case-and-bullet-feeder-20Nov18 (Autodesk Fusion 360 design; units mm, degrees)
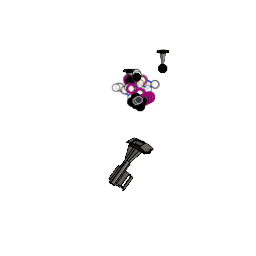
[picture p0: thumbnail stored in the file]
named bodies: "mk1j-bullet-base-feeder-beta", "mk1b-nose-guide", "mk1-flip-ramp", "mk1d-nose-guide-spacer", "mk2b-collator-plate-223", "mk1L-case-feeder-base-6-9", "mk1b-obsolete-case-feeder-base-centre", "mk1c-base-plate-attach", "mk1-case-to-pole-top", "mk1c-base-to-slinky-223cal-flange", "mk1j-base-wall-beta", "mk1L-case-feeder-base-9-12", "mk1L-case-feeder-base-12-3", "mk2L-case-feeder-centre-motor", "mk1b-case-side-6-9", "mk1b-case-side-3-6", "mk1c-case-side-9-12", "mk1e-case-collator-223-centre", "mk1e-case-plate-223-6-9", "mk1e-case-plate-223-9-12", "mk1e-case-plate-223-12-3", "mk1e-case-plate-223-3-6", "mk1b-bullet-steady-spring", "mk1d-lh-45deg-leg", "mk1d-rh-45deg-leg", "mk2b-recessed-collator-plate-223", "mk2c8-plus8mm-recessed-collator-plate-223", "mk2d-55gr-70deg-4mm-collator-plate-223", "mk1c-leg-rh-feet-extended", "mk1-original-flip-ramp (1)", "mk2-flip-ramp", "mk1b-nose-guide-spacer", "mk2g-62gr-70deg-3mm-collator-plate-223-beta", "mk2e-ii-62gr-70deg-4mm-collator-plate-223", "mk1-inside-scraper", "mk1-wall-9-12-case", "mk1c-wall-6-9-case", "mk1b-wall-3-6-case", "mk1d-case-fulcrum-223", "mk2b-plus-2mm-flip-ramp", "mk2b-plus-2mm-narrow-flip-ramp", "mk1c-leg-lh-feet-extended", "mk1c-leg-rh-feet-extended (1)", "mk1c-leg-rh-feet-extended (2)", "mk1b-bullet-collator-bench-stand-bottom", "mk1k-control-case-base", "mk1L-control-case-top", "mk1L-dowel-clamp", "mk1b-bullet-support-bracket", "mk1b-bullet-stand-top", "mk1g-case-feeder-base-9-12 (1)", "mk1g-case-feeder-base-6-9 (1)", "mk1g-case-feeder-base-3-6 (1)", "mk1L-case-feeder-base-3-6", "mk1b-9-12-6-9-wall-joiner", "mk1b-3-6-6-9-wall-joiner", "mk1b-case-guide-wall-joiner", "mk1b-case-feeder-test-base", "mk1-shute-switch-holder", "mk1-case-plate-308-6-9-beta"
